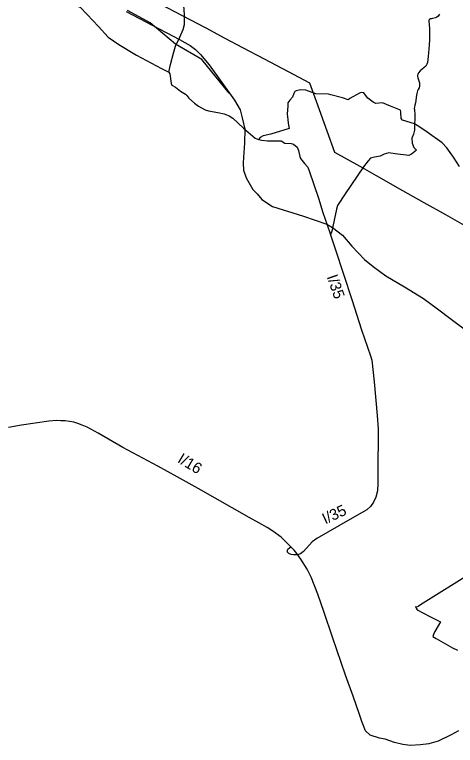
# Model space of a CAD drawing. Extents: x -789162 to -606354, y -1062736 to -945481.
# Drawn here: x -677029 to -671022, y -1014858 to -1004905 of the extents above; entities that cross this region are included whole.
import ezdxf

# ---------------------------------------------------------------- set-up
doc = ezdxf.new("R2010")
doc.units = 0
for name, color, linetype in [('_SIRSI VZTAHY_ELEKTRICKE VEDENI VN 400 kV S', 7, 'Continuous'), ('_SIRSI VZTAHY_SILNICE I a II TRIDY_STAV POPIS', 7, 'Continuous'), ('_SIRSI VZTAHY_SILNICE I TRIDY_NAVRH', 7, 'Continuous'), ('_SIRSI VZTAHY_SILNICE I TRIDY_STAV', 7, 'Continuous'), ('_SIRSI VZTAHY_SILNICE II TRIDY_STAV', 7, 'Continuous'), ('_SIRSI VZTAHY_SILNICE III TRIDY_STAV', 7, 'Continuous'), ('_SIRSI VZTAHY_VTL PLYNOVOD', 7, 'Continuous')]:
    doc.layers.add(name, color=color, linetype=linetype)

msp = doc.modelspace()

# ---------------------------------------------------------------- linework, layer by layer
at = {"layer": '_SIRSI VZTAHY_ELEKTRICKE VEDENI VN 400 kV S'}
msp.add_lwpolyline([(-670866.2, -1007795.1), (-671154.3, -1007632.8), (-671449.4, -1007466.7), (-671736.8, -1007304.7), (-672096.1, -1007102.1), (-672321.2, -1006975.3), (-672664.7, -1006781.7), (-672768.8, -1006493.5), (-672914.8, -1006088.8), (-673005.3, -1005838.5), (-673296.2, -1005684.9), (-673625.6, -1005510.9), (-673919.8, -1005355.2), (-674157.7, -1005229.6), (-674419.6, -1005091.3), (-674741.7, -1004920.9), (-675034.9, -1004766.1)], dxfattribs=at)
at = {"layer": '_SIRSI VZTAHY_SILNICE I TRIDY_NAVRH'}
msp.add_lwpolyline([(-675507.2, -1004862), (-674780.2, -1005243), (-674634.8, -1005326.9), (-674565.1, -1005380.2), (-674495.5, -1005449.8), (-674376.7, -1005587), (-674032.7, -1006070.4), (-673956.9, -1006203.5), (-673926.2, -1006312), (-673893.4, -1006463.6), (-673897.5, -1006656.1), (-673911.8, -1006846.5), (-673913.9, -1006928.5), (-673909.8, -1007024.7), (-673872.9, -1007127.1), (-673782.4, -1007285.2), (-673725.5, -1007344.2), (-673658.5, -1007423), (-673512.5, -1007520.3), (-673090.6, -1007649.3), (-672775.2, -1007759.9), (-672695.3, -1007805), (-672562.2, -1007907.4), (-672433.2, -1008058.9), (-672259.1, -1008239.2), (-672143, -1008335.4), (-671968.3, -1008462.4), (-671714.3, -1008613.9), (-671456.3, -1008773.7), (-671267.9, -1008912.9), (-671081.5, -1009054.3), (-670831.7, -1009240.6)], dxfattribs=at)
at = {"layer": '_SIRSI VZTAHY_SILNICE I TRIDY_STAV'}
for points in [[(-677007.3, -1004513.7), (-676940.1, -1004546.4), (-676862.3, -1004588.8), (-676796.8, -1004626), (-676715.4, -1004682.6), (-676644.7, -1004707.3), (-676600.4, -1004714.4), (-676411.1, -1004732.1), (-676352.8, -1004741), (-676294.4, -1004751.6), (-676200.6, -1004779.9), (-676136.9, -1004802.9), (-676041.4, -1004902), (-675887.5, -1005066.5), (-675754.8, -1005211.5), (-675609.7, -1005312.4), (-675365.6, -1005459.2), (-675163.9, -1005567.1), (-675027.7, -1005637.9), (-674925.1, -1005687.4)], [(-674925.1, -1005687.4), (-674914.5, -1005712.2), (-674896.8, -1005841.3), (-674885.9, -1005865.8), (-674834.9, -1005894.4), (-674767.6, -1005945.7), (-674700.4, -1005988.2), (-674682.7, -1006005.9), (-674654.1, -1006044.4), (-674576.6, -1006110.3), (-674523.5, -1006152.7), (-674433.3, -1006202.2), (-674385.5, -1006216.4), (-674258.1, -1006239.4), (-674173.2, -1006257.1), (-674104.2, -1006285.4), (-674052.9, -1006317.2), (-673907.9, -1006451.7), (-673750.4, -1006589.7), (-673706.2, -1006607.4)], [(-673706.2, -1006607.4), (-673662, -1006616.2), (-673580.6, -1006625.1), (-673437.3, -1006623.3), (-673398.4, -1006625.1), (-673345.3, -1006655.1), (-673260.4, -1006660.4), (-673230.3, -1006667.5), (-673177.2, -1006711.7), (-673159.5, -1006754.2), (-673143.6, -1006835.6), (-673131.2, -1006863.9), (-673076.4, -1006934.7), (-673032.1, -1006984.2), (-673014.5, -1007032), (-672888.9, -1007407), (-672826.9, -1007598.1), (-672734.9, -1007874.1), (-672724.3, -1007905.9)], [(-672724.3, -1007905.9), (-672660.6, -1008097), (-672432.4, -1008786.9), (-672299.7, -1009199.1), (-672181.2, -1009551.2), (-672161.7, -1009611.3), (-672129.9, -1009905), (-672089.2, -1010366.7), (-672076.8, -1010548.9), (-672073.3, -1010686.9), (-672080.4, -1011017.8), (-672078.6, -1011286.7), (-672082.1, -1011392.8), (-672105.1, -1011477.7), (-672137, -1011544.9), (-672179.4, -1011603.3), (-672230.7, -1011649.3), (-672459, -1011782), (-672911.8, -1012042.1), (-672972, -1012088.1), (-673090.5, -1012217.2), (-673133, -1012247.3), (-673174.7, -1012261.2), (-673226.6, -1012263.5), (-673260.3, -1012259.8), (-673294.1, -1012245), (-673309, -1012224.6), (-673312.2, -1012201.5), (-673305, -1012186.8), (-673283.5, -1012169.1), (-673264.1, -1012154.7)], [(-673264.1, -1012154.7), (-673331.9, -1012086.4), (-673397.3, -1012022.5), (-673509.8, -1011941.9), (-673588.9, -1011888.7), (-673701.5, -1011826.4), (-673830.7, -1011753.4), (-674527.2, -1011358), (-674814.7, -1011198.3), (-675076.2, -1011053.8), (-675552.2, -1010802.9), (-675891.4, -1010603.7), (-676040.4, -1010524.6), (-676108.8, -1010495.7), (-676165.1, -1010472.9), (-676221.4, -1010456.2), (-676279.2, -1010445.5), (-676340, -1010437.9), (-676400.8, -1010436.4), (-676458.6, -1010434.9), (-676560.5, -1010440.9), (-676933.1, -1010498.7), (-677112.5, -1010529.2)], [(-670980, -1014662.1), (-671079.1, -1014715.2), (-671256, -1014800.1), (-671385.1, -1014835.5), (-671500.1, -1014851.4), (-671638.1, -1014858.5), (-671738.9, -1014846.1), (-671853.9, -1014819.6), (-671979.5, -1014771.8), (-672057.4, -1014759.4), (-672184.7, -1014718.7), (-672246.7, -1014660.3), (-672298, -1014533), (-672329.8, -1014437.4), (-672416.5, -1014189.8), (-672519.1, -1013901.4), (-672696, -1013386.6), (-672812.8, -1013050.5), (-672897.7, -1012797.5), (-672989.7, -1012569.3), (-673041, -1012457.8), (-673129.1, -1012322.2), (-673184.4, -1012243.1), (-673221, -1012201), (-673264.1, -1012154.7)]]:
    msp.add_lwpolyline(points, dxfattribs=at)
at = {"layer": '_SIRSI VZTAHY_SILNICE II TRIDY_STAV'}
msp.add_lwpolyline([(-670509.5, -1012327.9), (-671354.1, -1012854.9), (-671497.5, -1012945.7), (-671531.8, -1012968.5), (-671552.4, -1012974.2), (-671566.1, -1012969.7), (-671558.1, -1012989.1), (-671544.4, -1013013.1), (-671370.8, -1013102.2), (-671225.7, -1013177.5), (-671303.4, -1013306.6), (-671322.8, -1013350), (-671329.6, -1013374), (-671282.8, -1013404.8), (-671060.1, -1013530.4), (-670992.7, -1013562.4)], dxfattribs=at)
at = {"layer": '_SIRSI VZTAHY_SILNICE III TRIDY_STAV'}
for points in [[(-674925.1, -1005687.4), (-674903.6, -1005584.9), (-674863.3, -1005428.3), (-674835.8, -1005335.1), (-674776.6, -1005210.3), (-674730, -1005108.7), (-674715.2, -1005038.8), (-674715.2, -1004907.6), (-674723.6, -1004774.2)], [(-671240, -1004896.4), (-671257.1, -1004923.9), (-671275.6, -1004939.7), (-671292.3, -1004950), (-671332.1, -1004959), (-671346.8, -1004960.4), (-671362.2, -1004963.1), (-671375.9, -1004969.6), (-671383.4, -1004981.2), (-671384.3, -1005002.8), (-671382, -1005031.2), (-671376.1, -1005106.9), (-671373, -1005198.5), (-671374.5, -1005254.7), (-671378.8, -1005312.1), (-671384.7, -1005373.9), (-671389.7, -1005420.3), (-671393.7, -1005475.3), (-671396.9, -1005515.9), (-671402.3, -1005556.5), (-671410.4, -1005578.1), (-671426.2, -1005605.2), (-671446.9, -1005625), (-671479.4, -1005652), (-671503.6, -1005672.6), (-671524.4, -1005698.9), (-671535.1, -1005718.2), (-671537.7, -1005731.5), (-671539.9, -1005748.9), (-671536.4, -1005765.4), (-671520.2, -1005807.3), (-671513.5, -1005835), (-671511.6, -1005857.2), (-671512.6, -1005877.2), (-671518.3, -1005902.9), (-671528.8, -1005925.5), (-671538, -1005943.9), (-671544.6, -1005962), (-671549.1, -1005977.2), (-671553.5, -1006002.6), (-671557, -1006035.6), (-671562.4, -1006074.7), (-671568.1, -1006108.3), (-671575.4, -1006138.8), (-671580.8, -1006165.5), (-671582.4, -1006181.4), (-671581.8, -1006197.2), (-671579.3, -1006220.7), (-671576.1, -1006249), (-671574.8, -1006275.3), (-671573.9, -1006299.2), (-671576.1, -1006328.4), (-671578.9, -1006392.5), (-671579.1, -1006480.2), (-671591.8, -1006535.2), (-671617.2, -1006586), (-671610.9, -1006653.7), (-671587.6, -1006715.1), (-671553.7, -1006753.2)], [(-670967.4, -1006973.4), (-671047.9, -1006848.5), (-671141, -1006717.2), (-671202.4, -1006651.6), (-671405.6, -1006507.7), (-671505.1, -1006435.7), (-671578.9, -1006392.5), (-671742.1, -1006344.7), (-671763.3, -1006319.3), (-671765.4, -1006234.6), (-671771.8, -1006205), (-671907.2, -1006150), (-672017.3, -1006105.5), (-672106.2, -1006116.1), (-672144.3, -1006099.2), (-672214.1, -1006044.1), (-672248, -1006001.8), (-672271.3, -1005967.9), (-672307.3, -1005963.7), (-672330.6, -1005974.3), (-672459.7, -1006048.4), (-672483, -1006067.4), (-672559.2, -1006039.9), (-672720, -1005995.5), (-672751.8, -1005987), (-672925.3, -1005984.9), (-673058.7, -1005934.1), (-673132.8, -1005927.7), (-673192, -1005942.5), (-673211.1, -1005953.1), (-673221.7, -1005978.5), (-673242.8, -1006029.3), (-673276.7, -1006071.7), (-673304.2, -1006105.5), (-673304.2, -1006147.9), (-673314.8, -1006260), (-673306.3, -1006332), (-673300, -1006384.9), (-673291.5, -1006431.5), (-673289.4, -1006456.9), (-673539.2, -1006533.1), (-673642.9, -1006556.4), (-673683.1, -1006579.7), (-673706.2, -1006607.4)], [(-671553.7, -1006753.2), (-671619.4, -1006806.1), (-671657.5, -1006825.2), (-671841.6, -1006799.8), (-671928.4, -1006789.2), (-671991.9, -1006804), (-672049, -1006831.5), (-672125.2, -1006844.2), (-672178.2, -1006861.2), (-672212, -1006895), (-672275.5, -1006979.7), (-672525.3, -1007345.9), (-672629, -1007502.5), (-672641.7, -1007555.4), (-672705.2, -1007856), (-672724.3, -1007905.9)]]:
    msp.add_lwpolyline(points, dxfattribs=at)
at = {"layer": '_SIRSI VZTAHY_VTL PLYNOVOD'}
msp.add_lwpolyline([(-674105.9, -1005976.6), (-674478.2, -1005514.4), (-674835, -1005309.4), (-675180.9, -1005015.1), (-675490.3, -1004850.5)], dxfattribs=at)

# ---------------------------------------------------------------- texts
at = {"layer": '_SIRSI VZTAHY_SILNICE I a II TRIDY_STAV POPIS'}
for s, rotation, p in [('I/35', 289.27138, (-672776.9, -1008475)), ('I/16', 328.84397, (-674820.6, -1010996.2)), ('I/35', 25.14174, (-672794.6, -1011849.8))]:
    msp.add_text(s, height=150, rotation=rotation, dxfattribs=at).set_placement(p)

doc.saveas('drawing.dxf')
